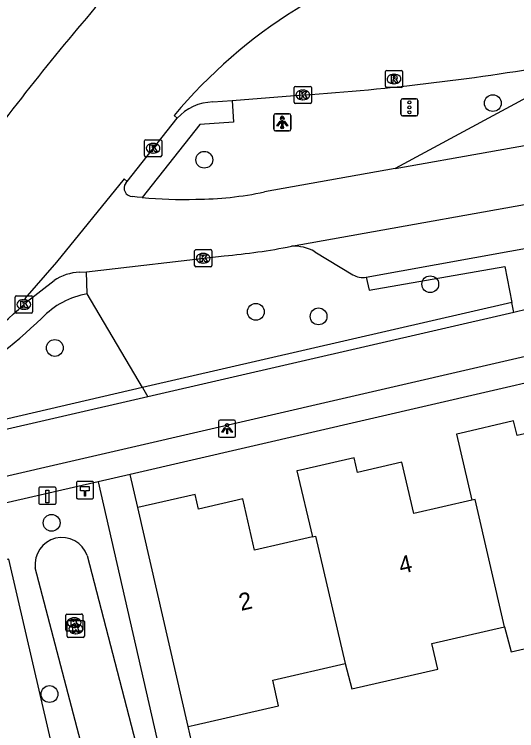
# Model space of a CAD drawing. Extents: x 156414 to 157775, y 382335 to 383765.
# Drawn here: x 156677.38 to 156706.59, y 382884.93 to 382926.61 of the extents above; entities that cross this region are included whole.
import ezdxf

# ---------------------------------------------------------------- set-up
doc = ezdxf.new("R2010")
doc.units = 0
for name, color, linetype in [('IMGEO_Berm_groen', 7, 'Continuous'), ('IMGEO_Boom', 7, 'Continuous'), ('IMGEO_Fietspad_gesloten', 7, 'Continuous'), ('IMGEO_Greppel_droge_sloot', 7, 'Continuous'), ('IMGEO_Haag', 7, 'Continuous'), ('IMGEO_Hectometerpaal', 7, 'Continuous'), ('IMGEO_Kolk', 7, 'Continuous'), ('IMGEO_Lichtpunt', 7, 'Continuous'), ('IMGEO_OVBaan_gesloten', 7, 'Continuous'), ('IMGEO_Paal', 7, 'Continuous'), ('IMGEO_Pand', 7, 'Continuous'), ('IMGEO_Pand_nummerreeks', 7, 'Continuous'), ('IMGEO_Parkeervlak_open', 7, 'Continuous'), ('IMGEO_Rijbaan_lokaal_gesloten', 7, 'Continuous'), ('IMGEO_Rijbaan_regionaal_gesloten', 7, 'Continuous'), ('IMGEO_Rioolput', 7, 'Continuous'), ('IMGEO_Verkeerseiland_open', 7, 'Continuous'), ('IMGEO_Verkeersregelinstallatiepaal', 7, 'Continuous'), ('IMGEO_Voetpad_open', 7, 'Continuous')]:
    doc.layers.add(name, color=color, linetype=linetype)

msp = doc.modelspace()

# ---------------------------------------------------------------- linework, layer by layer
at = {"layer": 'IMGEO_Berm_groen'}
for points in [[(156711.629, 382924.18), (156699.533, 382917.637)], [(156684.838, 382904.892), (156681.627, 382910.347)]]:
    msp.add_lwpolyline(points, dxfattribs=at)
at = {"layer": 'IMGEO_Boom'}
for centre in [(156705.203, 382921.444), (156688.428, 382918.148), (156701.564, 382910.905), (156691.424, 382909.303), (156695.072, 382909.035), (156679.741, 382907.199), (156679.552, 382897.029), (156679.426, 382887.065)]:
    msp.add_circle(centre, 0.489, dxfattribs=at)
at = {"layer": 'IMGEO_Fietspad_gesloten'}
for points in [[(156674.773, 382899.258), (156767.182, 382920.602), (156826.292, 382934.262), (156902.955, 382951.999), (156911.251, 382953.909)], [(156706.422, 382909.267), (156685.15, 382904.363)], [(156707.213, 382909.45), (156706.422, 382909.267)], [(156685.15, 382904.363), (156675.452, 382902.127)]]:
    msp.add_lwpolyline(points, dxfattribs=at)
at = {"layer": 'IMGEO_Greppel_droge_sloot'}
for points in [[(156681.618, 382895.117), (156687.407, 382872.758), (156687.607, 382870.105), (156685.253, 382870.145)], [(156684.85, 382870.502), (156678.6, 382894.402)]]:
    msp.add_lwpolyline(points, dxfattribs=at)
msp.add_arc((156680.145, 382894.61), 1.558, 19, 187.6566, dxfattribs=at)
at = {"layer": 'IMGEO_Haag'}
for points in [[(156706.31, 382909.849), (156684.838, 382904.892)], [(156684.838, 382904.892), (156675.327, 382902.697), (156675.452, 382902.127)], [(156684.838, 382904.892), (156685.15, 382904.363)]]:
    msp.add_lwpolyline(points, dxfattribs=at)
at = {"layer": 'IMGEO_Hectometerpaal'}
for p, q in [((156680.994, 382899.346), (156680.994, 382898.505)), ((156680.994, 382899.346), (156680.994, 382898.505)), ((156681.91, 382899.43), (156681.069, 382899.43)), ((156681.91, 382899.43), (156681.069, 382899.43)), ((156681.994, 382898.514), (156681.994, 382899.355)), ((156681.994, 382898.514), (156681.994, 382899.355)), ((156681.078, 382898.43), (156681.919, 382898.43)), ((156681.078, 382898.43), (156681.919, 382898.43))]:
    msp.add_line(p, q, dxfattribs=at)
msp.add_lwpolyline([(156681.519, 382898.574), (156681.459, 382898.574), (156681.459, 382898.879), (156681.239, 382898.879), (156681.239, 382899.148), (156681.739, 382899.148), (156681.739, 382898.879), (156681.519, 382898.879), (156681.519, 382898.574)], dxfattribs=at)
for centre, start, end in [((156681.072, 382899.352), 92.4484, 184.2845), ((156681.072, 382899.352), 92.4484, 184.2845), ((156681.916, 382899.352), 2.4484, 94.2845), ((156681.916, 382899.352), 2.4484, 94.2845), ((156681.072, 382898.508), 182.4484, 274.2845), ((156681.072, 382898.508), 182.4484, 274.2845), ((156681.916, 382898.508), 272.4484, 4.2845), ((156681.916, 382898.508), 272.4484, 4.2845)]:
    msp.add_arc(centre, 0.0779, start, end, dxfattribs=at)
at = {"layer": 'IMGEO_Kolk'}
for p, q in [((156693.655, 382921.491), (156693.655, 382922.343)), ((156693.73, 382922.417), (156694.582, 382922.417)), ((156694.143, 382922.197), (156694.168, 382922.197)), ((156694.656, 382922.343), (156694.656, 382921.491)), ((156694.582, 382921.417), (156693.73, 382921.417)), ((156694.166, 382921.637), (156694.141, 382921.637)), ((156685.025, 382919.314), (156685.877, 382919.314)), ((156684.95, 382918.388), (156684.95, 382919.24)), ((156685.438, 382919.094), (156685.463, 382919.094)), ((156685.951, 382919.24), (156685.951, 382918.388)), ((156685.461, 382918.534), (156685.436, 382918.534)), ((156685.877, 382918.314), (156685.025, 382918.314)), ((156687.866, 382911.992), (156687.866, 382912.844)), ((156687.941, 382912.918), (156688.793, 382912.918)), ((156688.354, 382912.698), (156688.379, 382912.698)), ((156688.867, 382912.844), (156688.867, 382911.992)), ((156688.793, 382911.918), (156687.941, 382911.918)), ((156688.377, 382912.138), (156688.352, 382912.138)), ((156677.438, 382909.301), (156677.438, 382910.153)), ((156677.513, 382910.227), (156678.365, 382910.227)), ((156678.439, 382910.153), (156678.439, 382909.301)), ((156677.926, 382910.007), (156677.951, 382910.007)), ((156677.949, 382909.447), (156677.924, 382909.447)), ((156678.365, 382909.227), (156677.513, 382909.227)), ((156680.369, 382890.796), (156680.369, 382891.648)), ((156680.444, 382891.722), (156681.296, 382891.722)), ((156680.53, 382891.352), (156681.382, 382891.352)), ((156680.857, 382891.502), (156680.882, 382891.502)), ((156681.37, 382891.648), (156681.37, 382890.796)), ((156680.455, 382890.426), (156680.455, 382891.278)), ((156680.88, 382890.942), (156680.855, 382890.942)), ((156680.943, 382891.132), (156680.968, 382891.132)), ((156681.456, 382891.278), (156681.456, 382890.426)), ((156681.296, 382890.722), (156680.444, 382890.722)), ((156680.966, 382890.572), (156680.941, 382890.572)), ((156681.382, 382890.352), (156680.53, 382890.352))]:
    msp.add_line(p, q, dxfattribs=at)
for points in [[(156693.655, 382921.491), (156693.655, 382922.343)], [(156693.73, 382922.417), (156694.582, 382922.417)], [(156694.656, 382922.343), (156694.656, 382921.491)], [(156693.976, 382922.117), (156694.099, 382922.117), (156694.099, 382921.966), (156694.229, 382922.117), (156694.393, 382922.117), (156694.247, 382921.966), (156694.4, 382921.717), (156694.248, 382921.717), (156694.163, 382921.881), (156694.099, 382921.814), (156694.099, 382921.717), (156693.976, 382921.717), (156693.976, 382922.117)], [(156694.582, 382921.417), (156693.73, 382921.417)], [(156685.025, 382919.314), (156685.877, 382919.314)], [(156684.95, 382918.388), (156684.95, 382919.24)], [(156685.271, 382919.014), (156685.394, 382919.014), (156685.394, 382918.863), (156685.524, 382919.014), (156685.688, 382919.014), (156685.542, 382918.863), (156685.695, 382918.614), (156685.543, 382918.614), (156685.458, 382918.778), (156685.394, 382918.711), (156685.394, 382918.614), (156685.271, 382918.614), (156685.271, 382919.014)], [(156685.951, 382919.24), (156685.951, 382918.388)], [(156685.877, 382918.314), (156685.025, 382918.314)], [(156687.866, 382911.992), (156687.866, 382912.844)], [(156687.941, 382912.918), (156688.793, 382912.918)], [(156688.187, 382912.618), (156688.31, 382912.618), (156688.31, 382912.467), (156688.44, 382912.618), (156688.604, 382912.618), (156688.458, 382912.467), (156688.611, 382912.218), (156688.459, 382912.218), (156688.374, 382912.382), (156688.31, 382912.315), (156688.31, 382912.218), (156688.187, 382912.218), (156688.187, 382912.618)], [(156688.867, 382912.844), (156688.867, 382911.992)], [(156688.793, 382911.918), (156687.941, 382911.918)], [(156677.438, 382909.301), (156677.438, 382910.153)], [(156677.513, 382910.227), (156678.365, 382910.227)], [(156678.439, 382910.153), (156678.439, 382909.301)], [(156677.759, 382909.927), (156677.882, 382909.927), (156677.882, 382909.776), (156678.012, 382909.927), (156678.176, 382909.927), (156678.03, 382909.776), (156678.183, 382909.527), (156678.031, 382909.527), (156677.946, 382909.691), (156677.882, 382909.624), (156677.882, 382909.527), (156677.759, 382909.527), (156677.759, 382909.927)], [(156678.365, 382909.227), (156677.513, 382909.227)], [(156680.369, 382890.796), (156680.369, 382891.648)], [(156680.444, 382891.722), (156681.296, 382891.722)], [(156680.53, 382891.352), (156681.382, 382891.352)], [(156680.69, 382891.422), (156680.813, 382891.422), (156680.813, 382891.271), (156680.943, 382891.422), (156681.107, 382891.422), (156680.961, 382891.271), (156681.114, 382891.022), (156680.962, 382891.022), (156680.877, 382891.186), (156680.813, 382891.119), (156680.813, 382891.022), (156680.69, 382891.022), (156680.69, 382891.422)], [(156681.37, 382891.648), (156681.37, 382890.796)], [(156680.455, 382890.426), (156680.455, 382891.278)], [(156680.776, 382891.052), (156680.899, 382891.052), (156680.899, 382890.901), (156681.029, 382891.052), (156681.193, 382891.052), (156681.047, 382890.901), (156681.2, 382890.652), (156681.048, 382890.652), (156680.963, 382890.816), (156680.899, 382890.749), (156680.899, 382890.652), (156680.776, 382890.652), (156680.776, 382891.052)], [(156681.456, 382891.278), (156681.456, 382890.426)], [(156681.296, 382890.722), (156680.444, 382890.722)], [(156681.382, 382890.352), (156680.53, 382890.352)]]:
    msp.add_lwpolyline(points, dxfattribs=at)
for centre, start, end in [((156693.732, 382922.341), 91.552, 178.448), ((156693.732, 382922.341), 91.552, 178.448), ((156694.58, 382922.341), 1.552, 88.448), ((156694.58, 382922.341), 1.552, 88.448), ((156693.732, 382921.493), 181.552, 268.448), ((156693.732, 382921.493), 181.552, 268.448), ((156694.58, 382921.493), 271.552, 358.448), ((156694.58, 382921.493), 271.552, 358.448), ((156685.027, 382919.238), 91.552, 178.448), ((156685.027, 382919.238), 91.552, 178.448), ((156685.875, 382919.238), 1.552, 88.448), ((156685.875, 382919.238), 1.552, 88.448), ((156685.027, 382918.39), 181.552, 268.448), ((156685.027, 382918.39), 181.552, 268.448), ((156685.875, 382918.39), 271.552, 358.448), ((156685.875, 382918.39), 271.552, 358.448), ((156687.943, 382912.842), 91.552, 178.448), ((156687.943, 382912.842), 91.552, 178.448), ((156688.791, 382912.842), 1.552, 88.448), ((156688.791, 382912.842), 1.552, 88.448), ((156687.943, 382911.994), 181.552, 268.448), ((156687.943, 382911.994), 181.552, 268.448), ((156688.791, 382911.994), 271.552, 358.448), ((156688.791, 382911.994), 271.552, 358.448), ((156677.515, 382910.151), 91.552, 178.448), ((156677.515, 382910.151), 91.552, 178.448), ((156678.363, 382910.151), 1.552, 88.448), ((156678.363, 382910.151), 1.552, 88.448), ((156677.515, 382909.303), 181.552, 268.448), ((156677.515, 382909.303), 181.552, 268.448), ((156678.363, 382909.303), 271.552, 358.448), ((156678.363, 382909.303), 271.552, 358.448), ((156680.446, 382891.646), 91.552, 178.448), ((156680.446, 382891.646), 91.552, 178.448), ((156680.532, 382891.276), 91.552, 178.448), ((156680.532, 382891.276), 91.552, 178.448), ((156681.294, 382891.646), 1.552, 88.448), ((156681.294, 382891.646), 1.552, 88.448), ((156681.38, 382891.276), 1.552, 88.448), ((156681.38, 382891.276), 1.552, 88.448), ((156680.446, 382890.798), 181.552, 268.448), ((156680.446, 382890.798), 181.552, 268.448), ((156681.294, 382890.798), 271.552, 358.448), ((156681.294, 382890.798), 271.552, 358.448), ((156680.532, 382890.428), 181.552, 268.448), ((156680.532, 382890.428), 181.552, 268.448), ((156681.38, 382890.428), 271.552, 358.448), ((156681.38, 382890.428), 271.552, 358.448)]:
    msp.add_arc(centre, 0.0765, start, end, dxfattribs=at)
for centre, major_axis, ratio, start_param, end_param in [((156694.142, 382921.917), (-0.387, 0.002), 0.722429, 4.712389, 7.853982), ((156694.167, 382921.917), (-0.39, 0.002), 0.717154, 1.570796, 4.712389), ((156685.437, 382918.814), (-0.387, 0.002), 0.722429, 4.712389, 7.853982), ((156685.462, 382918.814), (-0.39, 0.002), 0.717154, 1.570796, 4.712389), ((156688.353, 382912.418), (-0.387, 0.002), 0.722429, 4.712389, 7.853982), ((156688.378, 382912.418), (-0.39, 0.002), 0.717154, 1.570796, 4.712389), ((156677.925, 382909.727), (-0.387, 0.002), 0.722429, 4.712389, 7.853982), ((156677.95, 382909.727), (-0.39, 0.002), 0.717154, 1.570796, 4.712389), ((156680.856, 382891.222), (-0.387, 0.002), 0.722429, 4.712389, 7.853982), ((156680.881, 382891.222), (-0.39, 0.002), 0.717154, 1.570796, 4.712389), ((156680.942, 382890.852), (-0.387, 0.002), 0.722429, 4.712389, 7.853982), ((156680.967, 382890.852), (-0.39, 0.002), 0.717154, 1.570796, 4.712389)]:
    msp.add_ellipse(centre, major_axis=major_axis, ratio=ratio, start_param=start_param, end_param=end_param, dxfattribs=at)
at = {"layer": 'IMGEO_Lichtpunt'}
for p, q in [((156692.464, 382920.725), (156692.464, 382919.918)), ((156692.464, 382920.725), (156692.464, 382919.918)), ((156693.366, 382920.82), (156692.558, 382920.82)), ((156693.366, 382920.82), (156692.558, 382920.82)), ((156693.46, 382919.918), (156693.46, 382920.725)), ((156693.46, 382919.918), (156693.46, 382920.725)), ((156692.558, 382919.824), (156693.366, 382919.824)), ((156692.558, 382919.824), (156693.366, 382919.824)), ((156689.253, 382902.903), (156689.253, 382902.096)), ((156689.253, 382902.903), (156689.253, 382902.096)), ((156690.155, 382902.998), (156689.347, 382902.998)), ((156690.155, 382902.998), (156689.347, 382902.998)), ((156690.249, 382902.096), (156690.249, 382902.903)), ((156690.249, 382902.096), (156690.249, 382902.903)), ((156689.347, 382902.002), (156690.155, 382902.002)), ((156689.347, 382902.002), (156690.155, 382902.002))]:
    msp.add_line(p, q, dxfattribs=at)
for points in [[(156692.838, 382920.389), (156692.877, 382920.361), (156692.689, 382920.099), (156692.651, 382920.126), (156692.838, 382920.389)], [(156692.94, 382920.341), (156692.987, 382920.341), (156692.987, 382920.019), (156692.94, 382920.019), (156692.94, 382920.341)], [(156693.05, 382920.361), (156693.088, 382920.388), (156693.275, 382920.126), (156693.236, 382920.098), (156693.05, 382920.361)], [(156689.627, 382902.567), (156689.666, 382902.539), (156689.478, 382902.277), (156689.44, 382902.304), (156689.627, 382902.567)], [(156689.729, 382902.519), (156689.776, 382902.519), (156689.776, 382902.197), (156689.729, 382902.197), (156689.729, 382902.519)], [(156689.839, 382902.539), (156689.877, 382902.566), (156690.064, 382902.304), (156690.025, 382902.276), (156689.839, 382902.539)]]:
    msp.add_lwpolyline(points, dxfattribs=at)
for centre in [(156692.963, 382920.523), (156689.752, 382902.701)]:
    msp.add_circle(centre, 0.0994, dxfattribs=at)
for centre, start, end in [((156692.558, 382920.725), 90, 180), ((156692.558, 382920.725), 90, 180), ((156693.366, 382920.725), 0, 90), ((156693.366, 382920.725), 0, 90), ((156692.558, 382919.918), 180, 270), ((156692.558, 382919.918), 180, 270), ((156693.366, 382919.918), 270, 0), ((156693.366, 382919.918), 270, 360), ((156689.347, 382902.903), 90, 180), ((156689.347, 382902.903), 90, 180), ((156690.155, 382902.903), 0, 90), ((156690.155, 382902.903), 0, 90), ((156689.347, 382902.096), 180, 270), ((156689.347, 382902.096), 180, 270), ((156690.155, 382902.096), 270, 0), ((156690.155, 382902.096), 270, 360)]:
    msp.add_arc(centre, 0.0946, start, end, dxfattribs=at)
at = {"layer": 'IMGEO_OVBaan_gesloten'}
for points in [[(156683.945, 382916.882), (156686.844, 382920.562)], [(156686.844, 382920.562), (156686.676, 382920.729)], [(156683.945, 382916.882), (156683.778, 382917.046), (156679.836, 382912.189), (156677.988, 382910.077), (156678.152, 382909.917)], [(156677.937, 382909.73), (156678.152, 382909.917)]]:
    msp.add_lwpolyline(points, dxfattribs=at)
for centre, radius, start, end in [((156709.581, 382901.543), 29.878, 103.8905, 140.0495), ((156784.848, 382838.547), 135.58, 137.76022, 143.16252), ((156659.324, 382929.187), 26.926, 286.2025, 313.731)]:
    msp.add_arc(centre, radius, start, end, dxfattribs=at)
at = {"layer": 'IMGEO_Paal'}
for p, q in [((156678.807, 382899.02), (156678.807, 382898.179)), ((156678.807, 382899.02), (156678.807, 382898.179)), ((156679.723, 382899.104), (156678.882, 382899.104)), ((156679.723, 382899.104), (156678.882, 382899.104)), ((156679.807, 382898.188), (156679.807, 382899.029)), ((156679.807, 382898.188), (156679.807, 382899.029)), ((156678.891, 382898.104), (156679.732, 382898.104)), ((156678.891, 382898.104), (156679.732, 382898.104))]:
    msp.add_line(p, q, dxfattribs=at)
msp.add_lwpolyline([(156679.222, 382898.917), (156679.382, 382898.917), (156679.382, 382898.184), (156679.222, 382898.184), (156679.222, 382898.917)], dxfattribs=at)
for centre, start, end in [((156678.885, 382899.026), 92.4484, 184.2845), ((156678.885, 382899.026), 92.4484, 184.2845), ((156679.729, 382899.026), 2.4484, 94.2845), ((156679.729, 382899.026), 2.4484, 94.2845), ((156678.885, 382898.182), 182.4484, 274.2845), ((156678.885, 382898.182), 182.4484, 274.2845), ((156679.729, 382898.182), 272.4484, 4.2845), ((156679.729, 382898.182), 272.4484, 4.2845)]:
    msp.add_arc(centre, 0.0779, start, end, dxfattribs=at)
at = {"layer": 'IMGEO_Pand'}
for points in [[(156713.238, 382900.482), (156709.875, 382899.712), (156709.184, 382902.695), (156706.609, 382902.103), (156706.412, 382902.96), (156703.279, 382902.22), (156703.092, 382902.176), (156703.972, 382898.336)], [(156703.972, 382898.336), (156700.609, 382897.566), (156699.918, 382900.549), (156697.343, 382899.957), (156697.146, 382900.814), (156694.011, 382900.094), (156693.817, 382900.05), (156694.716, 382896.205)], [(156694.716, 382896.205), (156691.353, 382895.435), (156690.662, 382898.418), (156688.087, 382897.826), (156687.892, 382898.683), (156684.566, 382897.921)], [(156705.883, 382890.982), (156704.169, 382898.381), (156703.972, 382898.336)], [(156687.498, 382885.175), (156684.566, 382897.921)], [(156694.716, 382896.205), (156694.902, 382896.248), (156696.617, 382888.842)], [(156705.883, 382890.982), (156706.274, 382889.512), (156711.253, 382890.662), (156710.911, 382892.143), (156715.13, 382893.118)], [(156696.617, 382888.842), (156697.008, 382887.369), (156701.997, 382888.521), (156701.654, 382890.005), (156705.883, 382890.982)], [(156687.498, 382885.175), (156687.83, 382885.252), (156692.749, 382886.388), (156692.407, 382887.869), (156696.617, 382888.842)]]:
    msp.add_lwpolyline(points, dxfattribs=at)
at = {"layer": 'IMGEO_Parkeervlak_open'}
msp.add_lwpolyline([(156694.855, 382912.796), (156697.063, 382911.454)], dxfattribs=at)
for centre, radius, start, end in [((156693.658, 382910.738), 2.381, 59.8156, 94.0173), ((156697.646, 382912.479), 1.179, 240.3789, 279.479)]:
    msp.add_arc(centre, radius, start, end, dxfattribs=at)
at = {"layer": 'IMGEO_Rijbaan_lokaal_gesloten'}
msp.add_lwpolyline([(156682.815, 382870.13), (156682.646, 382870.787), (156677.074, 382894.919), (156673.903, 382894.251)], dxfattribs=at)
at = {"layer": 'IMGEO_Rijbaan_regionaal_gesloten'}
for points in [[(156690.044, 382921.597), (156694.154, 382921.918)], [(156688.926, 382921.51), (156690.044, 382921.597)], [(156699.533, 382917.637), (156710.418, 382919.581)], [(156699.533, 382917.637), (156691.926, 382916.279)], [(156683.861, 382916.781), (156683.945, 382916.882)], [(156684.816, 382915.946), (156684.53, 382915.979), (156684.245, 382916.015)], [(156693.491, 382913.113), (156711.264, 382916.292)], [(156681.579, 382911.627), (156689.581, 382912.559)], [(156681.174, 382911.608), (156681.579, 382911.627)], [(156678.152, 382909.917), (156679.695, 382911.115)]]:
    msp.add_lwpolyline(points, dxfattribs=at)
for centre, radius, start, end in [((156684.675, 383063.787), 142.186, 273.82234, 279.9911), ((156689.011, 382918.563), 2.949, 91.6558, 137.3068), ((156684.25, 382916.497), 0.482, 143.8045, 269.4452), ((156687.119, 382940.346), 24.508, 264.609, 271.895), ((156687.897, 382935.027), 19.176, 270.0954, 282.1286), ((156686.424, 382948.915), 36.492, 274.9628, 281.1661), ((156681.316, 382908.716), 2.896, 92.8196, 124.0503)]:
    msp.add_arc(centre, radius, start, end, dxfattribs=at)
at = {"layer": 'IMGEO_Rioolput'}
for p, q in [((156698.956, 382922.42), (156698.956, 382923.272)), ((156699.031, 382923.346), (156699.883, 382923.346)), ((156699.444, 382923.126), (156699.469, 382923.126)), ((156699.957, 382923.272), (156699.957, 382922.42)), ((156699.883, 382922.346), (156699.031, 382922.346)), ((156699.467, 382922.566), (156699.442, 382922.566))]:
    msp.add_line(p, q, dxfattribs=at)
for points in [[(156698.956, 382922.42), (156698.956, 382923.272)], [(156699.031, 382923.346), (156699.883, 382923.346)], [(156699.545, 382923.044), (156699.293, 382923.046), (156699.293, 382922.646)], [(156699.957, 382923.272), (156699.957, 382922.42)], [(156699.293, 382922.646), (156699.417, 382922.646), (156699.417, 382922.808), (156699.428, 382922.808)], [(156699.471, 382922.965), (156699.417, 382922.965), (156699.417, 382922.884)], [(156699.417, 382922.884), (156699.469, 382922.884)], [(156699.475, 382922.779), (156699.546, 382922.646), (156699.686, 382922.646), (156699.621, 382922.772)], [(156699.883, 382922.346), (156699.031, 382922.346)]]:
    msp.add_lwpolyline(points, dxfattribs=at)
for centre, radius, start, end in [((156699.033, 382923.27), 0.0765, 91.552, 178.448), ((156699.033, 382923.27), 0.0765, 91.552, 178.448), ((156699.544, 382922.934), 0.109, 350.3612, 89.416), ((156699.881, 382923.27), 0.0765, 1.552, 88.448), ((156699.881, 382923.27), 0.0765, 1.552, 88.448), ((156699.427, 382922.755), 0.0533, 26.0293, 88.6989), ((156699.453, 382923.073), 0.19, 274.7715, 282.9687), ((156699.477, 382922.869), 0.0964, 77.0061, 93.1865), ((156699.491, 382922.926), 0.0378, 276.6634, 79.6772), ((156699.542, 382922.934), 0.112, 277.5842, 350.9817), ((156699.526, 382922.719), 0.108, 29.5134, 73.7905), ((156699.033, 382922.422), 0.0765, 181.552, 268.448), ((156699.033, 382922.422), 0.0765, 181.552, 268.448), ((156699.881, 382922.422), 0.0765, 271.552, 358.448), ((156699.881, 382922.422), 0.0765, 271.552, 358.448)]:
    msp.add_arc(centre, radius, start, end, dxfattribs=at)
for centre, major_axis, ratio, start_param, end_param in [((156699.443, 382922.846), (-0.387, 0.002), 0.722429, 4.712389, 7.853982), ((156699.468, 382922.846), (-0.39, 0.002), 0.717154, 1.570796, 4.712389)]:
    msp.add_ellipse(centre, major_axis=major_axis, ratio=ratio, start_param=start_param, end_param=end_param, dxfattribs=at)
at = {"layer": 'IMGEO_Verkeerseiland_open'}
for points in [[(156690.044, 382921.597), (156690.126, 382920.329), (156688.16, 382920.192), (156684.816, 382915.946)], [(156681.627, 382910.347), (156681.579, 382911.627)]]:
    msp.add_lwpolyline(points, dxfattribs=at)
for centre, radius, start, end in [((156682.461, 382905.585), 4.834, 99.9295, 136.1032), ((156659.397, 382929.213), 28.187, 286.0352, 313.9993)]:
    msp.add_arc(centre, radius, start, end, dxfattribs=at)
at = {"layer": 'IMGEO_Verkeersregelinstallatiepaal'}
for p, q in [((156699.855, 382920.796), (156699.855, 382921.596)), ((156699.855, 382921.596), (156699.855, 382920.796)), ((156699.955, 382921.696), (156700.745, 382921.696)), ((156700.745, 382921.696), (156699.955, 382921.696)), ((156700.845, 382921.596), (156700.845, 382920.796)), ((156700.845, 382920.796), (156700.845, 382921.596)), ((156692.462, 382919.922), (156692.462, 382920.722)), ((156692.462, 382920.722), (156692.462, 382919.922)), ((156692.562, 382920.822), (156693.352, 382920.822)), ((156693.352, 382920.822), (156692.562, 382920.822)), ((156693.452, 382920.722), (156693.452, 382919.922)), ((156693.452, 382919.922), (156693.452, 382920.722)), ((156700.745, 382920.696), (156699.955, 382920.696)), ((156699.955, 382920.696), (156700.745, 382920.696)), ((156693.352, 382919.822), (156692.562, 382919.822)), ((156692.562, 382919.822), (156693.352, 382919.822))]:
    msp.add_line(p, q, dxfattribs=at)
for centre in [(156700.35, 382921.486), (156700.35, 382921.196), (156700.35, 382920.906), (156692.957, 382920.612), (156692.957, 382920.322), (156692.957, 382920.032)]:
    msp.add_circle(centre, 0.085, dxfattribs=at)
for centre, start, end in [((156699.955, 382921.596), 90, 180), ((156699.955, 382921.596), 90, 180), ((156700.745, 382921.596), 0, 90), ((156700.745, 382921.596), 360, 90), ((156692.562, 382920.722), 90, 180), ((156692.562, 382920.722), 90, 180), ((156693.352, 382920.722), 0, 90), ((156693.352, 382920.722), 360, 90), ((156699.955, 382920.796), 180, 270), ((156699.955, 382920.796), 180, 270), ((156700.745, 382920.796), 270, 0), ((156700.745, 382920.796), 270, 0), ((156692.562, 382919.922), 180, 270), ((156692.562, 382919.922), 180, 270), ((156693.352, 382919.922), 270, 0), ((156693.352, 382919.922), 270, 0)]:
    msp.add_arc(centre, 0.1, start, end, dxfattribs=at)
at = {"layer": 'IMGEO_Voetpad_open'}
for points in [[(156774.309, 382920.694), (156684.12, 382899.829)], [(156697.84, 382911.316), (156726.967, 382916.592)], [(156697.84, 382911.316), (156698.022, 382910.552), (156705.908, 382911.942), (156706.31, 382909.849)], [(156706.422, 382909.267), (156706.31, 382909.849)], [(156684.12, 382899.829), (156682.265, 382899.418)], [(156684.566, 382897.921), (156684.12, 382899.829)], [(156682.265, 382899.418), (156673.213, 382897.345)], [(156682.265, 382899.418), (156689.34, 382868.448)], [(156690.913, 382870.166), (156690.683, 382871.101), (156687.498, 382885.175)]]:
    msp.add_lwpolyline(points, dxfattribs=at)

# ---------------------------------------------------------------- texts
at = {"layer": 'IMGEO_Pand_nummerreeks'}
for s, p in [('4', (156699.863, 382894.045)), ('2', (156690.565, 382891.898))]:
    msp.add_text(s, height=1, rotation=13.0004, dxfattribs=at).set_placement(p)

doc.saveas('drawing.dxf')
